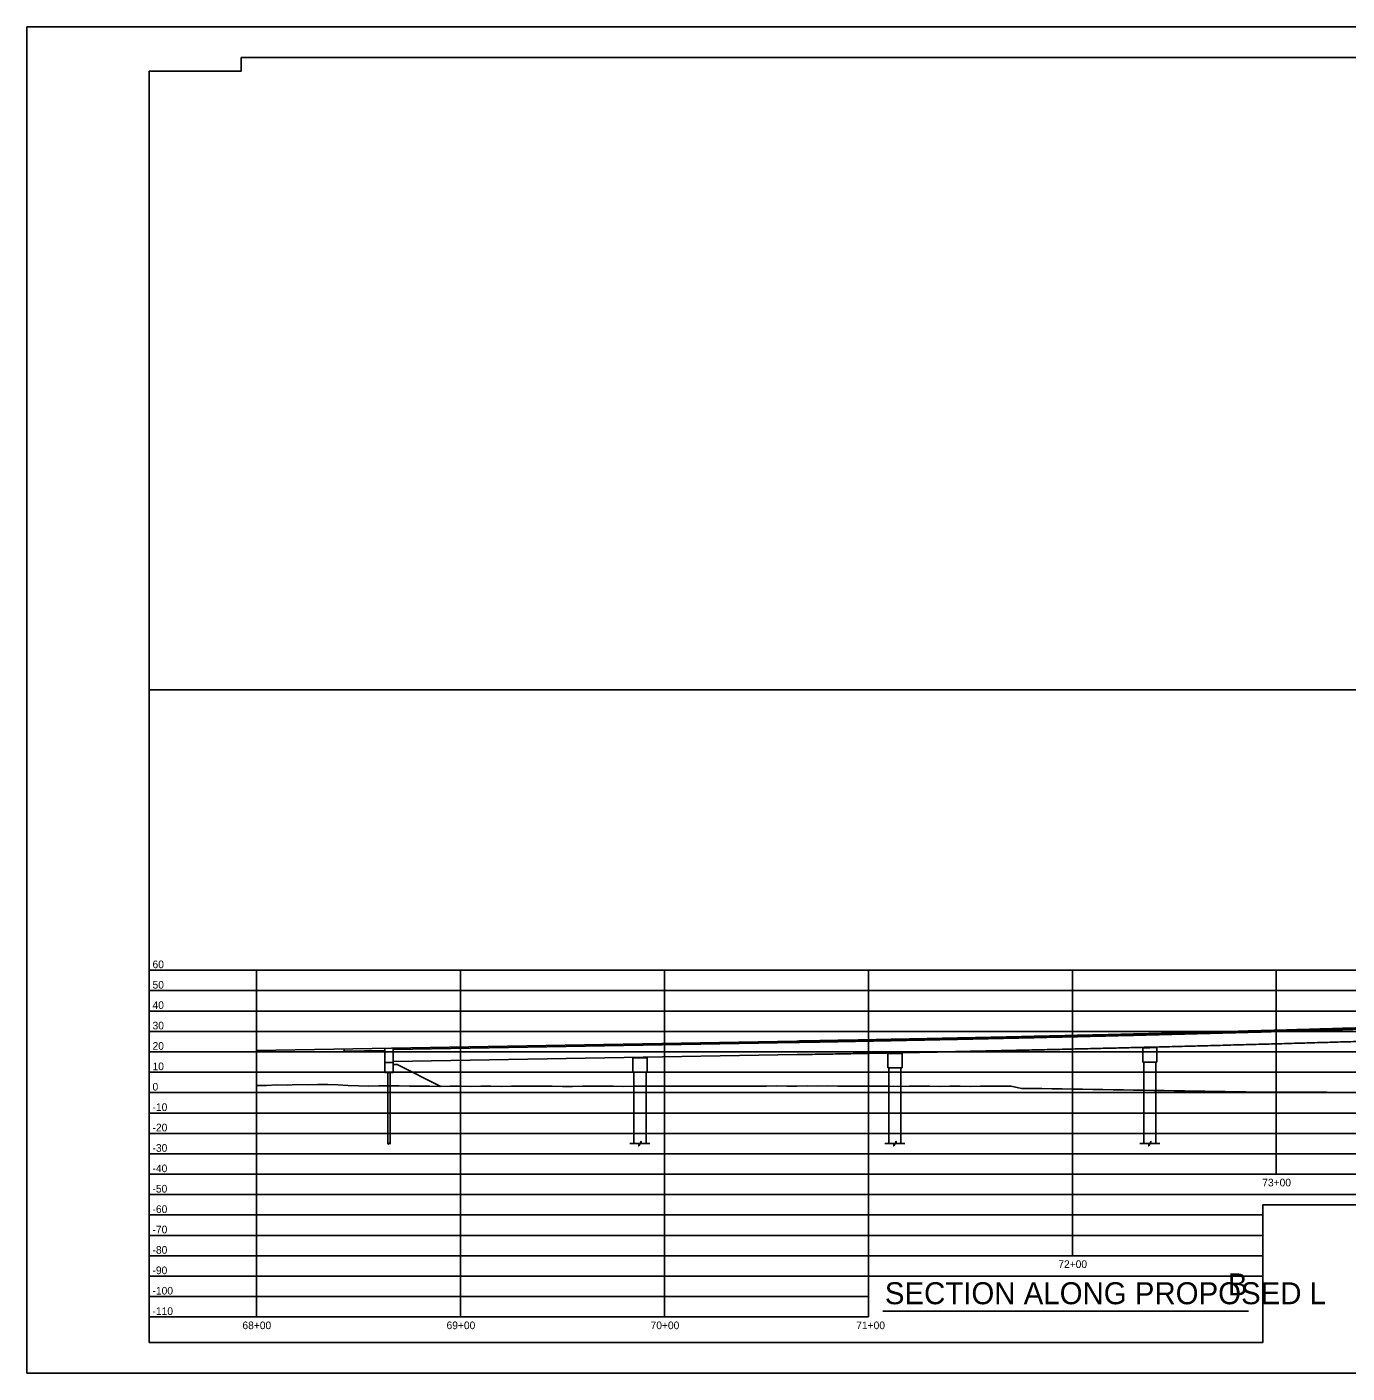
# Model space of a CAD drawing. Extents: x -464 to 4306, y -1372 to 300.
# Drawn here: x -464 to 183, y -1372 to -712 of the extents above; entities that cross this region are included whole.
import ezdxf

# ---------------------------------------------------------------- set-up
doc = ezdxf.new("R2010")
doc.units = 0
for name, color, linetype in [('BR_AUTO DIMENSION', 7, 'Continuous'), ('BR_BORDER LINES', 7, 'Continuous'), ('BR_GRID LINES', 7, 'Continuous'), ('BR_TEXT', 7, 'Continuous'), ('Mis Ground Lines', 7, 'Continuous'), ('Miscellaneous Lines', 7, 'Continuous'), ('NOPLOT', 7, 'Continuous'), ('Sheet Plot Border Outside CELL', 7, 'Continuous'), ('sub interior bent cap lines', 7, 'Continuous'), ('Sub Interior Bent Footing Line', 7, 'Continuous'), ('Sub Steel Pile Lines', 7, 'Continuous'), ('Sup Concrete Girder Lines', 7, 'Continuous'), ('Sup Concrete Slab Lines', 7, 'Continuous')]:
    doc.layers.add(name, color=color, linetype=linetype)

msp = doc.modelspace()

# ---------------------------------------------------------------- linework, layer by layer
at = {"layer": 'BR_AUTO DIMENSION'}
for points in [[(-287.36, -1259.94), (-286.66, -1259.94), (-286.66, -1260.26), (-286.34, -1259.62), (-286.34, -1259.94), (-285.64, -1259.94)], [(-168.38, -1259.94), (-164.06, -1259.94), (-164.06, -1261.06), (-162.94, -1258.83), (-162.94, -1259.94), (-158.63, -1259.94)], [(-43.38, -1259.94), (-39.06, -1259.94), (-39.06, -1261.06), (-37.94, -1258.83), (-37.94, -1259.94), (-33.63, -1259.94)], [(81.62, -1259.94), (85.94, -1259.94), (85.94, -1261.06), (87.06, -1258.83), (87.06, -1259.94), (91.37, -1259.94)]]:
    msp.add_lwpolyline(points, dxfattribs=at)
at = {"layer": 'BR_BORDER LINES'}
msp.add_line((-404, -1037.44), (601, -1037.44), dxfattribs=at)
at = {"layer": 'BR_GRID LINES'}
for p, q in [((-404, -1174.94), (601, -1174.94)), ((-351.5, -1344.94), (-351.5, -1174.94)), ((-251.5, -1344.94), (-251.5, -1174.94)), ((-151.5, -1344.94), (-151.5, -1174.94)), ((-51.5, -1344.94), (-51.5, -1174.94)), ((48.5, -1314.94), (48.5, -1174.94)), ((148.5, -1274.94), (148.5, -1174.94)), ((-404, -1184.94), (601, -1184.94)), ((-404, -1194.94), (601, -1194.94)), ((-404, -1204.94), (601, -1204.94)), ((-404, -1214.94), (601, -1214.94)), ((-404, -1224.94), (601, -1224.94)), ((-404, -1234.94), (601, -1234.94)), ((-404, -1244.94), (601, -1244.94)), ((-404, -1254.94), (601, -1254.94)), ((-404, -1264.94), (601, -1264.94)), ((-404, -1274.94), (376, -1274.94)), ((-404, -1284.94), (376, -1284.94)), ((-404, -1294.94), (141.93, -1294.94)), ((-404, -1304.94), (141.93, -1304.94)), ((-404, -1314.94), (141.93, -1314.94)), ((-404, -1324.94), (141.93, -1324.94)), ((-404, -1334.94), (-51.5, -1334.94)), ((-404, -1344.94), (-51.5, -1344.94))]:
    msp.add_line(p, q, dxfattribs=at)
at = {"layer": 'BR_TEXT'}
msp.add_line((-44.41, -1342.1), (134.85, -1342.1), dxfattribs=at)
at = {"layer": 'Mis Ground Lines'}
for p, q in [((-284.5, -1221.14), (-282.5, -1221.14)), ((-282.5, -1221.14), (-261.03, -1231.87))]:
    msp.add_line(p, q, dxfattribs=at)
for points in [[(-351.5, -1231.47), (-346.5, -1231.45), (-341.5, -1231.19), (-336.5, -1231.25), (-331.5, -1231.01), (-326.5, -1231.09), (-321.5, -1231.03), (-316.5, -1231.01), (-311.5, -1231.12), (-306.5, -1231.43), (-301.5, -1231.6), (-296.5, -1231.81), (-291.5, -1231.69), (-286.5, -1231.59), (-281.5, -1231.62), (-276.5, -1231.76), (-271.5, -1231.75), (-266.5, -1231.8), (-261.5, -1231.87), (-256.5, -1231.83), (-251.5, -1231.81), (-246.5, -1231.88), (-241.5, -1231.72), (-236.5, -1231.77), (-231.5, -1231.86), (-226.5, -1231.84), (-221.5, -1231.82), (-216.5, -1231.83), (-211.5, -1231.85), (-206.5, -1231.84), (-201.5, -1231.87), (-196.5, -1231.88), (-191.5, -1231.77), (-186.5, -1231.83), (-181.5, -1231.85), (-176.5, -1231.83), (-171.5, -1231.87), (-166.5, -1231.84), (-161.5, -1231.81), (-156.5, -1231.85), (-151.5, -1231.83)], [(-151.5, -1231.83), (-146.5, -1231.8), (-141.5, -1231.74), (-136.5, -1231.76), (-131.5, -1231.82), (-126.5, -1231.83), (-121.5, -1231.79), (-116.5, -1231.76), (-111.5, -1231.71), (-106.5, -1231.73), (-101.5, -1231.76), (-96.5, -1231.68), (-91.5, -1231.71), (-86.5, -1231.72), (-81.5, -1231.62), (-76.5, -1231.76), (-71.5, -1231.61), (-66.5, -1231.85), (-61.5, -1231.71), (-56.5, -1231.75), (-51.5, -1231.82), (-46.5, -1231.79), (-41.5, -1231.85), (-36.5, -1231.86), (-31.5, -1231.73), (-26.5, -1231.73), (-21.5, -1231.82), (-16.5, -1231.87), (-11.5, -1231.82), (-6.5, -1231.82), (-1.5, -1231.87), (3.5, -1231.76), (8.5, -1231.83), (13.5, -1231.78), (18.5, -1231.78), (23.5, -1232.89), (28.5, -1232.92), (33.5, -1233), (38.5, -1233.08), (43.5, -1233.15), (48.5, -1233.23), (53.5, -1233.31), (58.5, -1233.39), (63.5, -1233.47), (68.5, -1233.55), (73.5, -1233.63), (78.5, -1233.7), (83.5, -1233.78), (88.5, -1233.86), (93.5, -1233.94), (98.5, -1234.02), (103.5, -1234.09), (108.5, -1234.17), (113.5, -1234.25), (118.5, -1234.33), (123.5, -1234.41), (128.5, -1234.48), (133.5, -1234.56), (138.5, -1234.64), (143.5, -1234.72), (148.5, -1234.79), (153.5, -1234.79), (158.5, -1234.78), (163.5, -1234.78), (168.5, -1234.76), (173.5, -1234.79), (178.5, -1234.81), (183.5, -1234.83)]]:
    msp.add_lwpolyline(points, dxfattribs=at)
at = {"layer": 'Miscellaneous Lines'}
for p, q in [((-308.5, -1213.48), (-308.5, -1214.65)), ((-308.5, -1214.65), (-288.5, -1214.3))]:
    msp.add_line(p, q, dxfattribs=at)
at = {"layer": 'NOPLOT'}
msp.add_lwpolyline([(-359, -727.45), (-359, -734.19), (-404, -734.19), (-404, -1357.44), (141.93, -1357.44), (141.93, -1289.94), (376, -1289.94), (376, -1274.94), (601, -1274.94), (601, -747.45), (526, -747.45), (526, -727.45)], close=True, dxfattribs=at)
at = {"layer": 'Sheet Plot Border Outside CELL'}
msp.add_lwpolyline([(-464, -712.44), (616, -712.44), (616, -1372.44), (-464, -1372.44)], close=True, dxfattribs=at)
at = {"layer": 'sub interior bent cap lines'}
for p, q in [((90, -1212.9), (83, -1213.08)), ((83, -1213.08), (83, -1219.99)), ((90, -1212.9), (90, -1219.99)), ((-167, -1218.04), (-160, -1217.92)), ((-167, -1218.04), (-167, -1224.98)), ((-160, -1217.92), (-160, -1224.98)), ((-35, -1215.71), (-42, -1215.84)), ((-42, -1215.84), (-42, -1222.78)), ((-35, -1215.71), (-35, -1222.78)), ((83, -1219.99), (90, -1219.99)), ((83.5, -1219.99), (83.5, -1259.94)), ((89.5, -1219.99), (89.5, -1259.94)), ((-167, -1224.98), (-160, -1224.98)), ((-166.5, -1224.98), (-166.5, -1259.94)), ((-160.5, -1224.98), (-160.5, -1259.94)), ((-42, -1222.78), (-35, -1222.78)), ((-41.5, -1222.78), (-41.5, -1259.94)), ((-35.5, -1222.78), (-35.5, -1259.94))]:
    msp.add_line(p, q, dxfattribs=at)
at = {"layer": 'Sub Interior Bent Footing Line'}
for p, q in [((-288.5, -1213.14), (-288.5, -1225.14)), ((-284.5, -1213.07), (-284.5, -1225.14)), ((-288.5, -1220.14), (-284.5, -1220.14)), ((-288.5, -1225.14), (-284.5, -1225.14))]:
    msp.add_line(p, q, dxfattribs=at)
at = {"layer": 'Sub Steel Pile Lines'}
for p, q in [((-287.11, -1225.14), (-287.11, -1259.94)), ((-285.89, -1225.14), (-285.89, -1259.94))]:
    msp.add_line(p, q, dxfattribs=at)
at = {"layer": 'Sup Concrete Girder Lines'}
for p, q in [((-284.5, -1213.73), (-86.49, -1210.32)), ((-284.5, -1219.73), (-86.39, -1216.32))]:
    msp.add_line(p, q, dxfattribs=at)
for points in [[(-86.49, -1210.32), (-76.49, -1210.15), (-66.49, -1209.97), (-56.49, -1209.78), (-46.49, -1209.59), (-36.49, -1209.4), (-26.49, -1209.2), (-16.49, -1209), (-6.49, -1208.8), (3.51, -1208.58), (13.51, -1208.37), (23.51, -1208.15), (33.52, -1207.92), (43.52, -1207.69), (53.52, -1207.46), (63.52, -1207.22), (73.52, -1206.98), (83.52, -1206.73), (93.52, -1206.48), (103.52, -1206.22), (113.52, -1205.96), (123.52, -1205.7), (133.52, -1205.43), (143.52, -1205.15), (153.52, -1204.87), (163.52, -1204.59), (173.52, -1204.3), (183.52, -1204.01), (193.52, -1203.71), (203.52, -1203.41), (213.52, -1203.1), (223.52, -1202.79), (233.52, -1202.47), (243.52, -1202.15), (253.52, -1201.83), (263.52, -1201.5), (273.52, -1201.16), (283.52, -1200.83), (293.52, -1200.48), (303.52, -1200.14), (313.52, -1199.78), (323.52, -1199.43), (333.52, -1199.06), (343.52, -1198.7), (353.52, -1198.33), (363.53, -1197.95), (373.53, -1197.57), (383.53, -1197.19), (393.53, -1196.8), (403.53, -1196.41), (413.53, -1196.01)], [(-86.38, -1216.32), (-76.38, -1216.14), (-66.38, -1215.97), (-56.38, -1215.78), (-46.37, -1215.59), (-36.37, -1215.4), (-26.37, -1215.2), (-16.36, -1215), (-6.36, -1214.79), (3.64, -1214.58), (13.65, -1214.37), (23.65, -1214.15), (33.65, -1213.92), (43.65, -1213.69), (53.66, -1213.46), (63.66, -1213.22), (73.66, -1212.98), (83.67, -1212.73), (93.67, -1212.48), (103.67, -1212.22), (113.68, -1211.96), (123.68, -1211.69), (133.68, -1211.42), (143.68, -1211.15), (153.69, -1210.87), (163.69, -1210.59), (173.69, -1210.3), (183.7, -1210), (193.7, -1209.71), (203.7, -1209.4), (213.71, -1209.1), (223.71, -1208.79), (233.71, -1208.47), (243.71, -1208.15), (253.72, -1207.82), (263.72, -1207.5), (273.72, -1207.16), (283.73, -1206.82), (293.73, -1206.48), (303.73, -1206.13), (313.74, -1205.78), (323.74, -1205.42), (333.74, -1205.06), (343.75, -1204.7), (353.75, -1204.32), (363.75, -1203.95), (373.75, -1203.57), (383.76, -1203.19), (393.76, -1202.8), (403.76, -1202.4), (413.76, -1202.01)]]:
    msp.add_spline(points, degree=3, dxfattribs=at)
at = {"layer": 'Sup Concrete Slab Lines'}
msp.add_line((-351.5, -1214.22), (-86.5, -1209.65), dxfattribs=at)
msp.add_spline([(-86.5, -1209.65), (-76.5, -1209.48), (-66.5, -1209.3), (-56.5, -1209.12), (-46.5, -1208.93), (-36.5, -1208.73), (-26.5, -1208.54), (-16.5, -1208.34), (-6.5, -1208.13), (3.5, -1207.92), (13.5, -1207.7), (23.5, -1207.48), (33.5, -1207.26), (43.5, -1207.03), (53.5, -1206.79), (63.5, -1206.56), (73.5, -1206.31), (83.5, -1206.07), (93.5, -1205.81), (103.5, -1205.56), (113.5, -1205.3), (123.5, -1205.03), (133.5, -1204.76), (143.5, -1204.48), (153.5, -1204.21), (163.5, -1203.92), (173.5, -1203.63), (183.5, -1203.34), (193.5, -1203.04), (203.5, -1202.74), (213.5, -1202.43), (223.5, -1202.12), (233.5, -1201.81), (243.5, -1201.49), (253.5, -1201.16), (263.5, -1200.83), (273.5, -1200.5), (283.5, -1200.16), (293.5, -1199.82), (303.5, -1199.47), (313.5, -1199.12), (323.5, -1198.76), (333.5, -1198.4), (343.5, -1198.03), (353.5, -1197.66), (363.5, -1197.29), (373.5, -1196.91), (383.5, -1196.52), (393.5, -1196.14), (403.5, -1195.74), (413.5, -1195.34)], degree=3, dxfattribs=at)

# ---------------------------------------------------------------- texts
at = {"layer": 'BR_TEXT'}
for s, p in [('60', (-402.42, -1173.94)), ('50', (-402.42, -1183.94)), ('40', (-402.42, -1193.94)), ('30', (-402.42, -1203.94)), ('20', (-402.42, -1213.94)), ('10', (-402.42, -1223.94)), ('0', (-402.42, -1233.94)), ('-10', (-402.42, -1243.94)), ('-20', (-402.42, -1253.94)), ('-30', (-402.42, -1263.94)), ('-40', (-402.42, -1273.94)), ('-50', (-402.42, -1283.94)), ('73+00', (141.61, -1280.91)), ('-60', (-402.42, -1293.94)), ('-70', (-402.42, -1303.94)), ('-80', (-402.42, -1313.94)), ('72+00', (41.63, -1320.91)), ('-90', (-402.42, -1323.94)), ('-100', (-402.42, -1333.94)), ('-110', (-402.42, -1343.94)), ('68+00', (-358.34, -1350.91)), ('69+00', (-258.28, -1350.91)), ('70+00', (-158.25, -1350.91)), ('71+00', (-57.42, -1350.91))]:
    msp.add_text(s, height=3.75, rotation=360, dxfattribs=at).set_placement(p)
for s, height, p in [('B', 10.78, (124.74, -1334.33)), ('SECTION ALONG PROPOSED L', 10.7809, (-43.43, -1338.69))]:
    msp.add_text(s, height=height, dxfattribs=at).set_placement(p)

doc.saveas('drawing.dxf')
